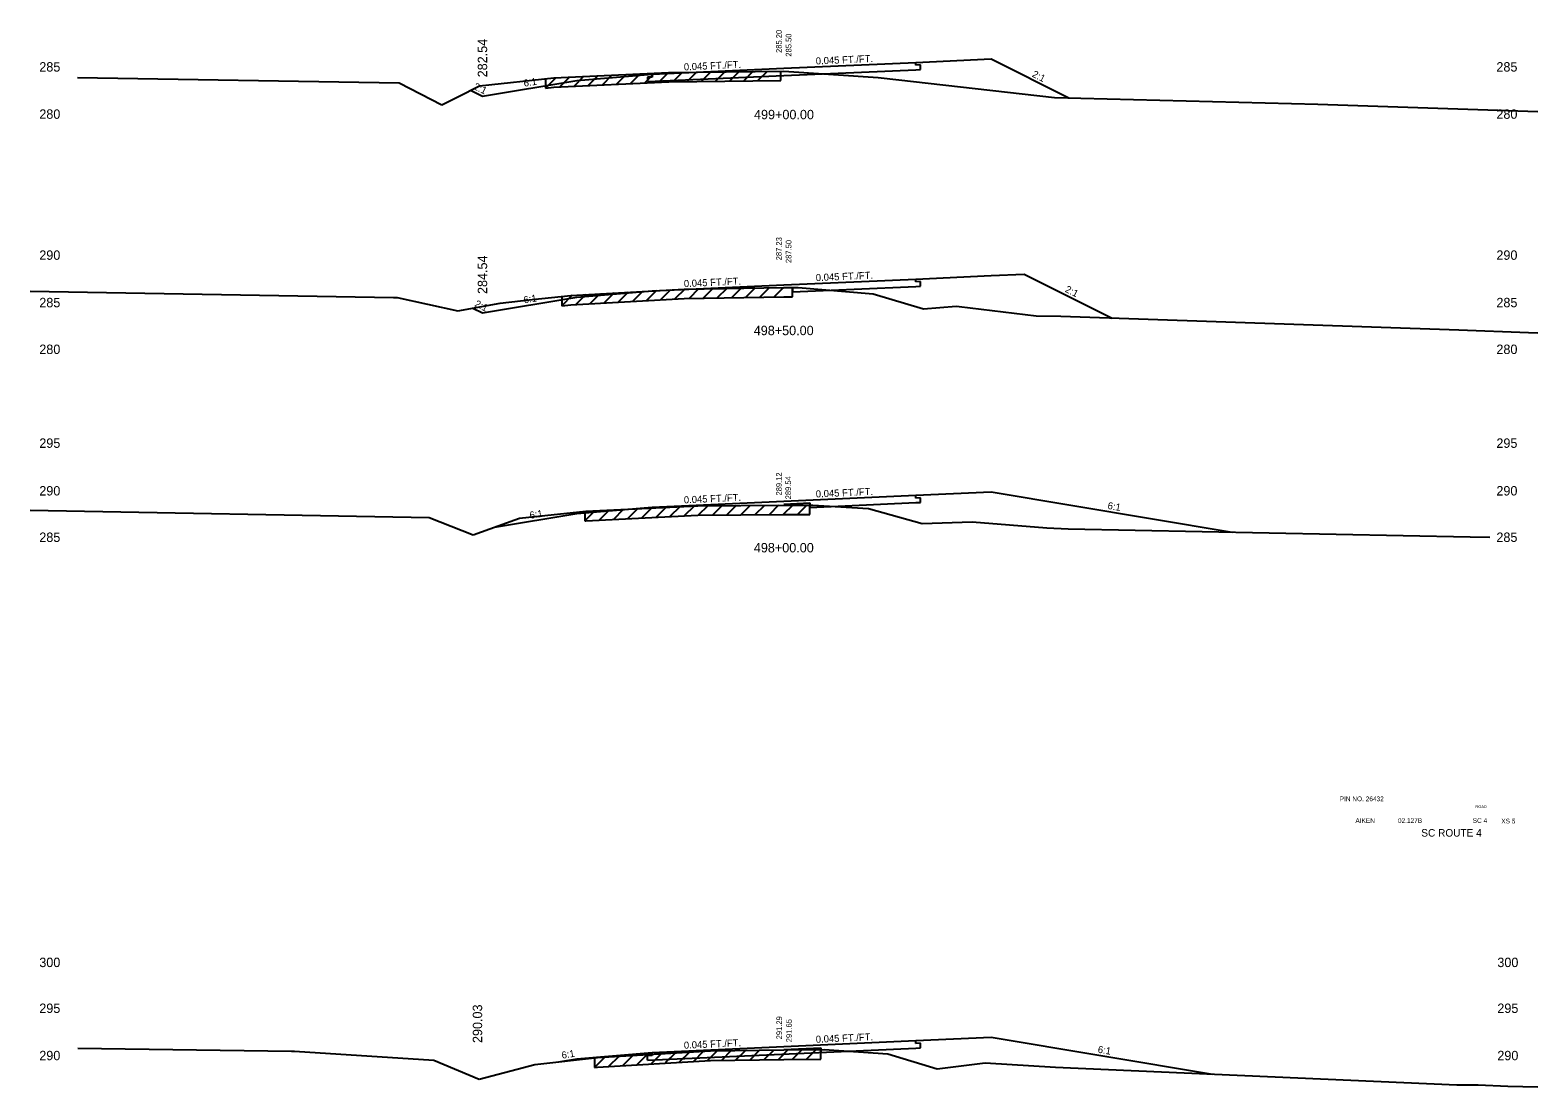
# Model space of a CAD drawing. Extents: x 883 to 1160, y 1002 to 4323.
# Drawn here: x 1000 to 1160, y 1532.4 to 1644.5 of the extents above; entities that cross this region are included whole.
import ezdxf

# ---------------------------------------------------------------- set-up
doc = ezdxf.new("R2010")
doc.units = 0
for name, color, linetype in [('Level 1', 7, 'Continuous'), ('Level 10', 7, 'Continuous'), ('Level 11', 7, 'Continuous'), ('Level 12', 7, 'Continuous'), ('Level 3', 7, 'Continuous'), ('Level 32', 7, 'Continuous'), ('Level 33', 7, 'Continuous'), ('Level 53', 7, 'Continuous'), ('Level 59', 7, 'Continuous'), ('Level 6', 7, 'Continuous'), ('Level 60', 7, 'Continuous'), ('Level 61', 7, 'Continuous'), ('Level 7', 7, 'Continuous')]:
    doc.layers.add(name, color=color, linetype=linetype)

msp = doc.modelspace()

# ---------------------------------------------------------------- linework, layer by layer
at = {"layer": 'Level 11'}
for p, q in [((1094, 1640.83), (1094, 1641.13)), ((1094.5, 1640.85), (1094, 1640.83)), ((1094, 1640.35), (1094.5, 1640.37)), ((1094.5, 1640.37), (1094.5, 1640.85)), ((1094, 1617.83), (1094, 1618.13)), ((1094.5, 1617.85), (1094, 1617.83)), ((1094.5, 1617.37), (1094.5, 1617.85)), ((1094, 1617.35), (1094.5, 1617.37)), ((1066, 1593.81), (1066, 1593.91)), ((1094, 1594.87), (1094, 1595.17)), ((1094.5, 1594.89), (1094, 1594.87)), ((1094, 1594.39), (1094.5, 1594.41)), ((1094.5, 1594.41), (1094.5, 1594.89)), ((1066, 1535.72), (1066, 1536.02)), ((1094, 1536.98), (1094, 1537.28)), ((1094.5, 1537), (1094, 1536.98)), ((1094, 1536.5), (1094.5, 1536.52)), ((1094.5, 1536.52), (1094.5, 1537)), ((1066, 1535.72), (1065.5, 1535.7)), ((1065.5, 1535.22), (1065.5, 1535.7))]:
    msp.add_line(p, q, dxfattribs=at)
at = {"layer": 'Level 12'}
for p, q in [((1080, 1639.72), (1094, 1640.35)), ((1065.5, 1639.09), (1080, 1639.72)), ((1066, 1639.57), (1065.5, 1639.57)), ((1065.5, 1639.57), (1065.5, 1639.09)), ((1066, 1639.87), (1066, 1639.57)), ((1080.9, 1616.76), (1094, 1617.35)), ((1080.9, 1617.24), (1080.9, 1616.76)), ((1082.75, 1593.88), (1094, 1594.39)), ((1082.75, 1594.13), (1082.75, 1593.88)), ((1065.5, 1535.22), (1094, 1536.5)), ((1083.91, 1536.33), (1083.91, 1536.04))]:
    msp.add_line(p, q, dxfattribs=at)
at = {"layer": 'Level 53'}
for p, q in [((1080, 1617.2), (1080.9, 1617.24)), ((1080.9, 1617.24), (1080.9, 1617.24)), ((1080, 1594.24), (1082.75, 1594.36)), ((1082.75, 1594.36), (1082.75, 1594.13)), ((1080, 1536.35), (1083.91, 1536.52)), ((1083.91, 1536.52), (1083.91, 1536.33))]:
    msp.add_line(p, q, dxfattribs=at)
at = {"layer": 'Level 59'}
for p, q in [((1066, 1639.87), (1080, 1640.5)), ((1080, 1640.5), (1094, 1641.13)), ((1080, 1617.5), (1094, 1618.13)), ((1066, 1616.87), (1080, 1617.5)), ((1066, 1593.91), (1080, 1594.54)), ((1080, 1594.54), (1094, 1595.17)), ((1066, 1536.02), (1080, 1536.65)), ((1080, 1536.65), (1094, 1537.28))]:
    msp.add_line(p, q, dxfattribs=at)
at = {"layer": 'Level 6'}
for p, q in [((1094, 1641.13), (1102, 1641.49)), ((1058, 1639.2), (1066, 1639.87)), ((1094, 1618.13), (1102, 1618.49)), ((1102, 1618.49), (1105.5, 1618.65)), ((1058, 1616.2), (1066, 1616.87)), ((1094, 1595.17), (1102, 1595.53)), ((1058, 1593.24), (1066, 1593.91)), ((1094, 1537.28), (1102, 1537.64)), ((1058, 1535.35), (1066, 1536.02))]:
    msp.add_line(p, q, dxfattribs=at)
at = {"layer": 'Level 60'}
for p, q in [((1055.56, 1639.48), (1067.77, 1640.05)), ((1067.77, 1640.05), (1080, 1640.2)), ((1080, 1640.2), (1090, 1639.51)), ((1005.01, 1639.52), (1039.16, 1638.96)), ((1039.16, 1638.96), (1043.7, 1636.61)), ((1045.39, 1637.48), (1047.67, 1638.64)), ((1047.67, 1638.64), (1055.56, 1639.48)), ((1090, 1639.51), (1090.31, 1639.48)), ((1090.31, 1639.48), (1108.7, 1637.41)), ((1043.7, 1636.61), (1045.39, 1637.48)), ((1108.7, 1637.41), (1136.66, 1636.7)), ((1136.66, 1636.7), (1139.85, 1636.58)), ((1139.85, 1636.58), (1160, 1635.93)), ((1000, 1616.83), (1038.57, 1616.18)), ((1038.57, 1616.18), (1038.96, 1616.18)), ((1038.96, 1616.18), (1045.4, 1614.75)), ((1053.28, 1615.95), (1057.38, 1616.39)), ((1057.38, 1616.39), (1069.41, 1617.06)), ((1069.41, 1617.06), (1080, 1617.23)), ((1080, 1617.23), (1081.5, 1617.24)), ((1081.5, 1617.24), (1089.45, 1616.57)), ((1089.45, 1616.57), (1094.82, 1614.96)), ((1045.4, 1614.75), (1049.87, 1615.58)), ((1049.87, 1615.58), (1053.28, 1615.95)), ((1094.82, 1614.96), (1098.27, 1615.26)), ((1098.27, 1615.26), (1098.58, 1615.23)), ((1098.58, 1615.23), (1106.77, 1614.23)), ((1106.77, 1614.23), (1109.38, 1614.18)), ((1109.38, 1614.18), (1151.62, 1612.75)), ((1151.62, 1612.75), (1159.01, 1612.45)), ((1159.01, 1612.45), (1160, 1612.43)), ((1000, 1593.6), (1042.34, 1592.82)), ((1058.98, 1593.47), (1070.87, 1594.05)), ((1070.87, 1594.05), (1080, 1594.12)), ((1080, 1594.12), (1083.07, 1594.13)), ((1083.07, 1594.13), (1088.97, 1593.77)), ((1088.97, 1593.77), (1094.68, 1592.17)), ((1042.34, 1592.82), (1047.01, 1590.97)), ((1047.01, 1590.97), (1051.45, 1592.57)), ((1051.45, 1592.57), (1051.93, 1592.74)), ((1051.93, 1592.74), (1058.98, 1593.47)), ((1094.68, 1592.17), (1099.96, 1592.37)), ((1099.96, 1592.37), (1107.88, 1591.71)), ((1107.88, 1591.71), (1110.14, 1591.61)), ((1110.14, 1591.61), (1152.81, 1590.76)), ((1152.81, 1590.76), (1154.92, 1590.71)), ((1005.06, 1536.47), (1027.74, 1536.15)), ((1027.74, 1536.15), (1028.07, 1536.15)), ((1028.07, 1536.15), (1042.84, 1535.22)), ((1060.22, 1535.48), (1072.2, 1536.19)), ((1072.2, 1536.19), (1080, 1536.29)), ((1080, 1536.29), (1084.25, 1536.34)), ((1084.25, 1536.34), (1091.03, 1535.87)), ((1042.84, 1535.22), (1047.66, 1533.2)), ((1051.01, 1534.08), (1053.57, 1534.76)), ((1053.57, 1534.76), (1060.22, 1535.48)), ((1091.03, 1535.87), (1096.25, 1534.28)), ((1096.25, 1534.28), (1101.35, 1534.94)), ((1101.35, 1534.94), (1108.82, 1534.46)), ((1108.82, 1534.46), (1151.41, 1532.58)), ((1047.66, 1533.2), (1051.01, 1534.08)), ((1151.41, 1532.58), (1153.66, 1532.59)), ((1153.66, 1532.59), (1156.83, 1532.46)), ((1156.83, 1532.46), (1160, 1532.38))]:
    msp.add_line(p, q, dxfattribs=at)
at = {"layer": 'Level 61'}
for p, q in [((1067.74, 1640.04), (1066.69, 1639)), ((1069.21, 1640.06), (1068.19, 1639.05)), ((1070.71, 1640.08), (1069.7, 1639.07)), ((1072.21, 1640.1), (1071.2, 1639.09)), ((1073.71, 1640.12), (1072.7, 1639.11)), ((1075.21, 1640.14), (1074.2, 1639.12)), ((1076.71, 1640.16), (1075.7, 1639.14)), ((1078.21, 1640.17), (1077.2, 1639.16)), ((1079.67, 1639.19), (1079.67, 1640.19)), ((1055.79, 1639.49), (1054.69, 1638.38)), ((1054.69, 1639.38), (1054.69, 1638.38)), ((1054.69, 1638.38), (1055.56, 1638.48)), ((1055.56, 1638.48), (1067.77, 1639.05)), ((1057.24, 1639.56), (1056.19, 1638.51)), ((1058.74, 1639.63), (1057.69, 1638.58)), ((1060.24, 1639.69), (1059.19, 1638.65)), ((1061.74, 1639.76), (1060.69, 1638.72)), ((1063.24, 1639.83), (1062.19, 1638.79)), ((1064.74, 1639.9), (1063.69, 1638.86)), ((1066.24, 1639.97), (1065.19, 1638.93)), ((1067.77, 1639.05), (1079.67, 1639.19)), ((1057.52, 1616.4), (1056.41, 1615.29)), ((1056.41, 1616.29), (1056.41, 1615.29)), ((1057.38, 1615.39), (1069.41, 1616.06)), ((1058.97, 1616.48), (1057.91, 1615.42)), ((1060.47, 1616.56), (1059.41, 1615.51)), ((1061.97, 1616.65), (1060.91, 1615.59)), ((1063.47, 1616.73), (1062.41, 1615.67)), ((1064.97, 1616.81), (1063.91, 1615.76)), ((1066.47, 1616.9), (1065.41, 1615.84)), ((1067.97, 1616.98), (1066.91, 1615.92)), ((1069.47, 1617.06), (1068.42, 1616.01)), ((1069.41, 1616.06), (1080, 1616.23)), ((1070.93, 1617.08), (1069.92, 1616.07)), ((1072.44, 1617.11), (1071.42, 1616.09)), ((1073.94, 1617.13), (1072.92, 1616.12)), ((1075.44, 1617.16), (1074.42, 1616.14)), ((1076.94, 1617.18), (1075.92, 1616.16)), ((1078.44, 1617.2), (1077.42, 1616.19)), ((1079.94, 1617.23), (1078.93, 1616.21)), ((1080, 1616.23), (1080.9, 1616.24)), ((1080.9, 1616.24), (1080.9, 1617.24)), ((1056.41, 1615.29), (1057.38, 1615.39)), ((1062.94, 1593.66), (1061.89, 1592.61)), ((1064.44, 1593.74), (1063.39, 1592.68)), ((1065.95, 1593.81), (1064.89, 1592.76)), ((1067.45, 1593.88), (1066.39, 1592.83)), ((1068.95, 1593.96), (1067.9, 1592.91)), ((1070.45, 1594.03), (1069.4, 1592.98)), ((1071.91, 1594.06), (1070.9, 1593.05)), ((1073.41, 1594.07), (1072.4, 1593.06)), ((1074.92, 1594.08), (1073.91, 1593.08)), ((1076.42, 1594.09), (1075.41, 1593.09)), ((1077.92, 1594.1), (1076.91, 1593.1)), ((1079.42, 1594.12), (1078.41, 1593.11)), ((1080.92, 1594.12), (1079.92, 1593.12)), ((1082.42, 1594.13), (1081.42, 1593.12)), ((1082.75, 1593.13), (1082.75, 1594.13)), ((1059.94, 1593.51), (1058.88, 1592.46)), ((1058.88, 1593.46), (1058.88, 1592.46)), ((1058.88, 1592.46), (1058.98, 1592.47)), ((1058.98, 1592.47), (1070.87, 1593.05)), ((1061.44, 1593.59), (1060.38, 1592.54)), ((1070.87, 1593.05), (1080, 1593.12)), ((1080, 1593.12), (1082.75, 1593.13)), ((1069.96, 1536.06), (1068.89, 1535)), ((1071.46, 1536.15), (1070.39, 1535.08)), ((1072.92, 1536.2), (1071.89, 1535.17)), ((1074.41, 1536.22), (1073.4, 1535.21)), ((1075.91, 1536.24), (1074.9, 1535.23)), ((1077.41, 1536.26), (1076.4, 1535.25)), ((1078.91, 1536.28), (1077.9, 1535.27)), ((1080.41, 1536.3), (1079.4, 1535.28)), ((1081.91, 1536.31), (1080.9, 1535.3)), ((1083.41, 1536.33), (1082.4, 1535.32)), ((1083.91, 1535.33), (1083.91, 1536.33)), ((1060.97, 1535.52), (1059.89, 1534.44)), ((1059.89, 1535.44), (1059.89, 1534.44)), ((1059.89, 1534.44), (1060.22, 1534.48)), ((1060.22, 1534.48), (1072.2, 1535.19)), ((1062.46, 1535.61), (1061.39, 1534.55)), ((1063.96, 1535.7), (1062.89, 1534.64)), ((1065.46, 1535.79), (1064.39, 1534.73)), ((1066.96, 1535.88), (1065.89, 1534.82)), ((1068.46, 1535.97), (1067.39, 1534.91)), ((1072.2, 1535.19), (1080, 1535.29)), ((1080, 1535.29), (1083.91, 1535.33))]:
    msp.add_line(p, q, dxfattribs=at)
at = {"layer": 'Level 7'}
for p, q in [((1102, 1641.49), (1110.24, 1637.37)), ((1048, 1637.54), (1058, 1639.2)), ((1046.74, 1638.17), (1048, 1637.54)), ((1105.5, 1618.65), (1114.81, 1613.99)), ((1048, 1614.54), (1058, 1616.2)), ((1046.98, 1615.04), (1048, 1614.54)), ((1102, 1595.53), (1127.56, 1591.27)), ((1049.27, 1591.79), (1058, 1593.24)), ((1102, 1537.64), (1125.49, 1533.72)), ((1056.06, 1535.03), (1058, 1535.35))]:
    msp.add_line(p, q, dxfattribs=at)

# ---------------------------------------------------------------- texts
at = {"layer": 'Level 1'}
for s, height, p in [('499+00.00', 1, (1076.82, 1635.09)), ('498+50.00', 1, (1076.79, 1612.17)), ('498+00.00', 1, (1076.8, 1589.11)), ('PIN NO. 26432', 0.5, (1138.97, 1562.7)), ('AIKEN', 0.5, (1140.64, 1560.39)), ('02.127B', 0.5, (1145.15, 1560.39)), ('SC 4', 0.5, (1153.09, 1560.39)), ('XS 5', 0.5, (1156.12, 1560.34)), ('SC ROUTE 4', 0.8, (1147.63, 1558.94))]:
    msp.add_text(s, height=height, dxfattribs=at).set_placement(p)
at = {"layer": 'Level 10'}
for s, p in [('285.20', (1079.76, 1642.13)), ('287.23', (1079.76, 1620.12)), ('289.12', (1079.76, 1595.15)), ('291.29', (1079.79, 1537.42))]:
    msp.add_text(s, height=0.6, rotation=90, dxfattribs=at).set_placement(p)
at = {"layer": 'Level 3'}
for s, height, p in [(' 285', 1, (1000.6, 1640.15)), (' 285', 1, (1155.23, 1640.15)), (' 280', 1, (1000.6, 1635.14)), (' 280', 1, (1155.23, 1635.14)), (' 290', 1, (1000.6, 1620.17)), (' 290', 1, (1155.23, 1620.17)), (' 285', 1, (1000.6, 1615.13)), (' 285', 1, (1155.23, 1615.13)), (' 280', 1, (1000.6, 1610.17)), (' 280', 1, (1155.23, 1610.17)), (' 295', 1, (1000.6, 1600.21)), (' 295', 1, (1155.23, 1600.21)), (' 290', 1, (1000.6, 1595.15)), (' 290', 1, (1155.23, 1595.15)), (' 285', 1, (1000.6, 1590.22)), (' 285', 1, (1155.23, 1590.22)), ('ROAD', 0.3, (1153.38, 1561.97)), (' 300', 1, (1000.6, 1545.09)), (' 300', 1, (1155.33, 1545.09)), (' 295', 1, (1000.6, 1540.22)), (' 295', 1, (1155.33, 1540.22)), (' 290', 1, (1000.6, 1535.2)), (' 290', 1, (1155.33, 1535.2))]:
    msp.add_text(s, height=height, dxfattribs=at).set_placement(p)
at = {"layer": 'Level 32'}
for s, rotation, p in [('0.045 FT./FT.', 2.5766, (1083.39, 1640.9)), ('0.045 FT./FT.', 2.5766, (1069.39, 1640.27)), ('2:1', 333.435, (1106.26, 1639.64)), ('2:1', 333.435, (1046.98, 1638.33)), ('6:1', 9.4623, (1052.43, 1638.53)), ('0.045 FT./FT.', 2.5766, (1069.39, 1617.27)), ('0.045 FT./FT.', 2.5766, (1083.39, 1617.9)), ('6:1', 9.4623, (1052.43, 1615.53)), ('2:1', 333.435, (1109.76, 1616.8)), ('2:1', 333.435, (1047.1, 1615.27)), ('0.045 FT./FT.', 2.5766, (1069.39, 1594.31)), ('0.045 FT./FT.', 2.5766, (1083.39, 1594.94)), ('6:1', 9.4623, (1053.07, 1592.67)), ('6:1', 350.5377, (1114.3, 1593.73)), ('0.045 FT./FT.', 2.5766, (1083.39, 1537.05)), ('6:1', 9.4623, (1056.46, 1535.35)), ('0.045 FT./FT.', 2.5766, (1069.39, 1536.42)), ('6:1', 350.5377, (1113.26, 1536.01))]:
    msp.add_text(s, height=0.75, rotation=rotation, dxfattribs=at).set_placement(p)
at = {"layer": 'Level 33'}
for s, p in [('282.54', (1048.5, 1639.54)), ('284.54', (1048.5, 1616.54)), ('290.03', (1047.97, 1537.03))]:
    msp.add_text(s, height=1, rotation=90, dxfattribs=at).set_placement(p)
at = {"layer": 'Level 59'}
for s, p in [(' 285.50', (1080.79, 1641.51)), (' 287.50', (1080.79, 1619.6)), (' 289.54', (1080.75, 1594.52)), (' 291.65', (1080.83, 1536.89))]:
    msp.add_text(s, height=0.6, rotation=90, dxfattribs=at).set_placement(p)

doc.saveas('drawing.dxf')
